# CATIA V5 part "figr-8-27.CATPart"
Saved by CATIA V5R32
Part number: Part2
Bounding box of the stored display mesh (mm): x -50 to 500, y -650 to 50, z 0 to 50
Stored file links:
  D:\PROJECTS\Project 2022\CATIA V5 6R 2022\Resources\Part Files\c08_catia_v5_6r2022_prt\figr-8-27.CATPart
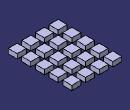
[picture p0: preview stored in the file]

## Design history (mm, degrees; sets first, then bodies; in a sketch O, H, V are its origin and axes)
Body1 (main body)
  Sketch1 on xy-plane, origin (0, 0, 0), H (1, 0, 0), V (0, 1, 0)
    line L1 (-50, 50) -> (50, 50)
    line L2 (50, 50) -> (50, -50)
    line L3 (50, -50) -> (-50, -50)
    line L4 (-50, -50) -> (-50, 50)
    axis line L5 (50, -50) -> (-50, 50)
    length L3 = 100
    length L2 = 100
    horizontal: L1 H, L3 H
    vertical: L2 V, L4 V
    midpoint: O L5
  Pad1: profile Sketch1, direction (0, 0, 1), length 50
  RectPattern1: of the body so far, direction 1 instances 4, spacing 150, along edge [face of Pad1 | face of Pad1], direction 2 instances 5, spacing 150, along edge [face of Pad1 | face of Pad1]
